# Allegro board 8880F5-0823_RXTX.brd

Outline 581.66 x 429.26 mm; copper layers: TOP, L02_DGND, L03_SIGNAL, L04_DGND, L05_SIGNAL, L06_DGND, L07_SIGNAL, L08_DGND, L09_SIGNAL, L10_DGND, L11_POWER, L12_DGND, L13_POWER, L14_DGND, L15_POWER, L16_DGND, L17_5V, L18_CBIT, L19_DGND, L20_POWER, L21_DGND, L22_POWER, L23_DGND, L24_POWER, L25_DGND, L26_SIGNAL, L27_DGND, L28_SIGNAL, L29_DGND, L30_SIGNAL, L31_DGND, L32_SIGNAL, L33_DGND, BOTTOM. Coordinates in mm from the lower left corner of the outline.

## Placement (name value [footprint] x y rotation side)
BD29  BD120-3A-S8  [FB0805]  129.54 134.62 180 bottom
BD30  BD120-3A-S8  [FB0805]  129.54 146.05 180 bottom
BD31  BD120-3A-S8  [FB0805]  129.54 142.24 0 bottom
BD32  BD120-3A-S8  [FB0805]  513.08 238.76 180 bottom
BD33  BD120-3A-S8  [FB0805]  513.08 242.57 180 bottom
BD34  BD120-3A-S8  [FB0805]  453.64 145.54 0 bottom
BD35  BD120-3A-S8  [FB0805]  453.64 137.92 180 bottom
BD36  BD120-3A-S8  [FB0805]  129.54 138.43 180 bottom
BD37  BD120-3A-S8  [FB0805]  453.64 130.3 180 bottom
BD38  BD120-3A-S8  [FB0805]  513.08 242.57 180 bottom
BD39  BD120-3A-S8  [FB0805]  453.64 141.73 0 bottom
BD40  BD120-3A-S8  [FB0805]  453.64 134.11 180 bottom
BD41  BD120-3A-S8  [FB0805]  513.08 234.95 180 bottom
BD42  BD120-3A-S8  [FB0805]  513.08 231.14 180 bottom
BD43  BD120-3A-S8  [FB0805]  513.08 227.33 180 bottom
BD44  BD120-3A-S8  [FB0805]  129.54 149.86 180 bottom
BR902  330-1-S4  [R0402]  36.83 133.35 270 bottom
C3  0.1U-16-X-S4-MU  [C0402]  184.15 132.33 180 bottom
C4  0.1U-16-X-S4-MU  [C0402]  181.61 132.33 180 bottom
C5  22P-50-N-S4-AVX  [C0402]  221.21 277.48 90 bottom
C6  22P-50-N-S4-AVX  [C0402]  221.21 271.16 270 bottom
C7  0.1U-16-X-S4-MU  [C0402]  110.74 230.12 0 bottom
C8  0.1U-16-X-S4-MU  [C0402]  104.14 215.5 180 bottom
C9  0.1U-16-X-S4-MU  [C0402]  104.24 229.1 180 bottom
CA1  NC/10U-10-X6S-S6-MU  [C0603]  186.05 292.1 0 bottom
CA2  NC/47U-10-X5R-S8-TDK  [C0805]  186.16 294 0 bottom
CA3  NC/10U-10-X6S-S6-MU  [C0603]  174.62 292.1 180 bottom
CA4  NC/47U-10-X5R-S8-TDK  [C0805]  174.52 294 180 bottom
CA5  NC/10U-10-X6S-S6-MU  [C0603]  117.47 290.83 180 bottom
CA6  NC/47U-10-X5R-S8-TDK  [C0805]  117.37 292.74 180 bottom
CA7  NC/10U-10-X6S-S6-MU  [C0603]  169.54 292.1 0 bottom
CA8  NC/47U-10-X5R-S8-TDK  [C0805]  169.65 294 0 bottom
CA9  NC/10U-10-X6S-S6-MU  [C0603]  158.11 292.1 180 bottom
CA10  NC/47U-10-X5R-S8-TDK  [C0805]  158.01 294 180 bottom
CA11  NC/10U-10-X6S-S6-MU  [C0603]  186.05 275.59 0 bottom
CA12  NC/47U-10-X5R-S8-TDK  [C0805]  186.16 277.5 0 bottom
CA13  NC/47U-10-X5R-S8-TDK  [C0805]  202.16 294 0 bottom
CA14  NC/10U-10-X6S-S6-MU  [C0603]  202.06 292.1 0 bottom
CA15  NC/47U-10-X5R-S8-TDK  [C0805]  190.53 294 180 bottom
CA16  NC/10U-10-X6S-S6-MU  [C0603]  190.63 292.1 180 bottom
CA17  NC/47U-10-X5R-S8-TDK  [C0805]  169.65 277.5 0 bottom
CA18  NC/10U-10-X6S-S6-MU  [C0603]  169.54 275.59 0 bottom
CA19  NC/47U-10-X5R-S8-TDK  [C0805]  100.34 249.52 180 bottom
CA20  NC/10U-10-X6S-S6-MU  [C0603]  100.44 247.61 180 bottom
CA21  10U-10-X6S-S6-MU  [C0603]  186.05 289.56 0 bottom
CA22  10U-10-X6S-S6-MU  [C0603]  174.62 289.56 180 bottom
CA23  10U-10-X6S-S6-MU  [C0603]  117.47 288.29 180 bottom
CA24  10U-10-X6S-S6-MU  [C0603]  169.54 289.56 0 bottom
CA25  10U-10-X6S-S6-MU  [C0603]  158.11 289.56 180 bottom
CA26  10U-10-X6S-S6-MU  [C0603]  186.05 273.05 0 bottom
CA27  10U-10-X6S-S6-MU  [C0603]  202.06 289.56 0 bottom
CA28  10U-10-X6S-S6-MU  [C0603]  190.63 289.56 180 bottom
CA29  10U-10-X6S-S6-MU  [C0603]  169.54 273.05 0 bottom
CA30  NC/47U-10-X5R-S8-TDK  [C0805]  95.47 249.57 180 bottom
CA31  10U-10-X6S-S6-MU  [C0603]  95.57 247.66 180 bottom
CA32  NC/10U-10-X6S-S6-MU  [C0603]  202.06 275.59 0 bottom
CA33  NC/47U-10-X5R-S8-TDK  [C0805]  202.16 277.5 0 bottom
CA34  10U-10-X6S-S6-MU  [C0603]  202.06 273.05 0 bottom
CA35  NC/10U-10-X6S-S6-MU  [C0603]  174.62 275.59 180 bottom
CA36  NC/47U-10-X5R-S8-TDK  [C0805]  174.52 277.5 180 bottom
CA37  10U-10-X6S-S6-MU  [C0603]  174.62 273.05 180 bottom
CA38  NC/10U-10-X6S-S6-MU  [C0603]  158.11 275.59 180 bottom
CA39  NC/47U-10-X5R-S8-TDK  [C0805]  158.01 277.5 180 bottom
CA40  10U-10-X6S-S6-MU  [C0603]  158.11 273.05 180 bottom
CB1  0.1U-25-X-S6  [C0603]  116.84 130.81 0 bottom
CB2  10U-16-T-SA  [CODE_A]  116.84 128.27 0 bottom
CB3  0.1U-25-X-S6  [C0603]  472.44 130.81 0 bottom
CB4  10U-16-T-SA  [CODE_A]  472.44 128.27 0 bottom
CB5  0.1U-25-X-S6  [C0603]  556.51 300.99 0 bottom
CB6  10U-16-T-SA  [CODE_A]  556.51 298.45 0 bottom
CB7  0.1U-25-X-S6  [C0603]  223.52 298.45 0 bottom
CB8  10U-16-T-SA  [CODE_A]  223.52 295.91 0 bottom
CB9  0.1U-25-X-S6  [C0603]  23.01 130.71 0 bottom
CB10  10U-25-X7R-SA  [C1206]  22.86 128.27 0 bottom
CB11  0.1U-25-X-S6  [C0603]  484.02 130.71 0 bottom
CB12  10U-25-X7R-SA  [C1206]  483.87 128.27 0 bottom
CB13  0.1U-25-X-S6  [C0603]  547.52 300.89 0 bottom
CB14  10U-25-X7R-SA  [C1206]  547.37 298.45 0 bottom
CB15  0.1U-25-X-S6  [C0603]  12.45 262.13 0 bottom
CB16  10U-25-X7R-SA  [C1206]  12.3 259.69 0 bottom
CB19  0.1U-25-X7R-S4-MU  [C0402]  215.9 17.78 180 bottom
CC1  0.47U-10-X6S-S2-TY  [C0201]  237.98 224.12 90 bottom
CC2  4.7U-10-X6T-S4-MU  [C0402]  236.32 222.4 270 bottom
CC4  0.47U-10-X6S-S2-TY  [C0201]  229.81 247.93 0 bottom
CC6  0.47U-10-X6S-S2-TY  [C0201]  250.17 224.12 90 bottom
CC7  0.47U-10-X6S-S2-TY  [C0201]  229.81 246.66 0 bottom
CC8  0.47U-10-X6S-S2-TY  [C0201]  263.63 224.12 90 bottom
CC9  0.47U-10-X6S-S2-TY  [C0201]  254.61 266.16 270 bottom
CC11  0.47U-10-X6S-S2-TY  [C0201]  251.06 224.12 90 bottom
CC13  0.47U-10-X6S-S2-TY  [C0201]  256.77 224.12 90 bottom
CC15  4.7U-2.5-X6S-S2-MU  [C0201]  259.65 264.95 90 bottom
CC16  NC/4.7U-2.5-X6S-S2-MU  [C0201]  271.64 249.5 0 bottom
CC17  4.7U-2.5-X6S-S2-MU  [C0201]  229.81 253.69 0 bottom
CC19  0.47U-10-X6S-S2-TY  [C0201]  252.83 266.16 270 bottom
CC20  4.7U-10-X6T-S4-MU  [C0402]  254.11 267.66 0 bottom
CC22  0.47U-10-X6S-S2-TY  [C0201]  251.05 266.16 270 bottom
CC23  4.7U-10-X6T-S4-MU  [C0402]  250.34 253.09 270 bottom
CC25  0.47U-10-X6S-S2-TY  [C0201]  272.85 245.18 180 bottom
CC26  0.47U-10-X6S-S2-TY  [C0201]  253.72 266.16 270 bottom
CC27  0.47U-10-X6S-S2-TY  [C0201]  272.85 249.5 180 bottom
CC28  0.47U-10-X6S-S2-TY  [C0201]  259.65 266.16 270 bottom
CC29  0.47U-10-X6S-S2-TY  [C0201]  231.03 253.69 180 bottom
CC30  0.47U-10-X6S-S2-TY  [C0201]  229.81 243.41 0 bottom
CC31  0.47U-10-X6S-S2-TY  [C0201]  249.28 224.12 90 bottom
CC32  0.47U-10-X6S-S2-TY  [C0201]  262.36 224.12 90 bottom
CC33  0.47U-10-X6S-S2-TY  [C0201]  272.85 243.91 180 bottom
CC34  0.47U-10-X6S-S2-TY  [C0201]  251.94 266.16 270 bottom
CC35  0.47U-10-X6S-S2-TY  [C0201]  272.85 241.37 180 bottom
CC36  0.47U-10-X6S-S2-TY  [C0201]  272.85 242.64 180 bottom
CC37  0.47U-10-X6S-S2-TY  [C0201]  247.57 264.95 90 bottom
CC38  NC/4.7U-2.5-X6S-S2-MU  [C0201]  247.57 266.16 270 bottom
CC39  0.47U-10-X6S-S2-TY  [C0201]  231.03 249.2 180 bottom
CC40  4.7U-2.5-X6S-S2-MU  [C0201]  258.5 246.67 180 bottom
CC41  4.7U-2.5-X6S-S2-MU  [C0201]  229.81 249.2 0 bottom
CC42  4.7U-2.5-X6S-S2-MU  [C0201]  251.54 253.03 90 bottom
CD1  0.1U-10-X7R-S2-MU  [C0201]  237.98 225.34 270 top
CD3  0.1U-10-X7R-S2-MU  [C0201]  271.64 241.37 0 top
CD4  0.1U-10-X7R-S2-MU  [C0201]  254.61 264.95 90 top
CD5  0.1U-10-X7R-S2-MU  [C0201]  263.63 225.34 270 top
CD6  0.1U-10-X7R-S2-MU  [C0201]  231.03 246.66 180 top
CD7  0.1U-10-X7R-S2-MU  [C0201]  271.64 242.64 0 top
CD8  0.1U-10-X7R-S2-MU  [C0201]  251.06 225.34 270 top
CD9  0.1U-10-X7R-S2-MU  [C0201]  256.77 225.34 270 top
CD10  0.1U-10-X7R-S2-MU  [C0201]  271.64 249.5 0 top
CD11  0.1U-10-X7R-S2-MU  [C0201]  259.65 264.95 90 top
CD12  0.1U-10-X7R-S2-MU  [C0201]  231.03 253.69 180 top
CD13  0.1U-10-X7R-S2-MU  [C0201]  252.83 264.95 90 top
CD14  0.1U-10-X7R-S2-MU  [C0201]  251.05 264.95 90 top
CD15  0.1U-10-X7R-S2-MU  [C0201]  271.64 245.18 0 top
CD16  0.1U-10-X7R-S2-MU  [C0201]  253.72 264.95 90 top
CD17  0.1U-10-X7R-S2-MU  [C0201]  231.03 247.93 180 top
CD18  0.1U-10-X7R-S2-MU  [C0201]  251.94 264.95 90 top
CD19  0.1U-10-X7R-S2-MU  [C0201]  231.03 243.41 180 top
CD20  0.1U-10-X7R-S2-MU  [C0201]  271.64 243.91 0 top
CD21  0.1U-10-X7R-S2-MU  [C0201]  262.36 225.34 270 top
CD22  0.1U-10-X7R-S2-MU  [C0201]  249.28 225.34 270 top
CD23  0.1U-10-X7R-S2-MU  [C0201]  250.17 225.34 270 top
CD24  0.1U-10-X7R-S2-MU  [C0201]  247.57 264.95 90 top
CD25  0.1U-10-X7R-S2-MU  [C0201]  231.03 249.2 180 top
CSDPS225  V93K_CSDPS_DPS32  [PG_VG93K_PF_DPS32_G8D225]  254 331.47 0 top
CSDPS229  V93K_CSDPS_DPS32  [PG_VG93K_PF_DPS32_G8D229]  180.34 331.47 0 top
CSDPS425  V93K_CSDPS_DPS32  [PG_VG93K_PF_DPS32_G8D425]  254 341.63 0 top
CSDPS429  V93K_CSDPS_DPS32  [PG_VG93K_PF_DPS32_G8D429]  180.34 341.63 0 top
D101/D501  V93K_PS1600 HD  [PG_VG93K_F_HSM_G1D101_501_ND]  327.66 97.79 0 top
D102  V93K_CH  [PG_VG93K_F_G1D102]  327.66 77.47 0 top
D103  V93K_CH  [PG_VG93K_F_G1D103]  327.66 57.15 0 top
D104  V93K_CH  [PG_VG93K_F_G1D104]  327.66 36.83 0 top
D105/D505  V93K_PS1600 HD  [PG_VG93K_F_HSM_G1D105_505_ND]  401.32 97.79 0 top
D106  V93K_CH  [PG_VG93K_F_G1D106]  401.32 77.47 0 top
D107  V93K_CH  [PG_VG93K_F_G1D107]  401.32 57.15 0 top
D108  V93K_CH  [PG_VG93K_F_G1D108]  401.32 36.83 0 top
D109  V93K_CH  [PG_VG93K_F_G2D109]  401.32 331.47 0 top
D110  V93K_CH  [PG_VG93K_F_G2D110]  401.32 351.79 0 top
D111  V93K_CH  [PG_VG93K_F_G2D111]  401.32 372.11 0 top
D112  V93K_CH  [PG_VG93K_F_G2D112]  401.32 392.43 0 top
D113  V93K_CH  [PG_VG93K_F_G2D113]  327.66 331.47 0 top
D114  V93K_CH  [PG_VG93K_F_G2D114]  327.66 351.79 0 top
D115  V93K_CH  [PG_VG93K_F_G2D115]  327.66 372.11 0 top
D116  V93K_CH  [PG_VG93K_F_G2D116]  327.66 392.43 0 top
D117/D517  V93K_PS1600 HD  [PG_VG93K_F_HSM_G3D117_517_ND]  180.34 97.79 0 top
D118  V93K_CH  [PG_VG93K_F_G3D118]  180.34 77.47 0 top
D119  V93K_CH  [PG_VG93K_F_G3D119]  180.34 57.15 0 top
D120  V93K_CH  [PG_VG93K_F_G3D120]  180.34 36.83 0 top
D121/D521  V93K_PS1600 HD  [PG_VG93K_F_HSM_G3D121_521_ND]  254 97.79 0 top
D122  V93K_CH  [PG_VG93K_F_G3D122]  254 77.47 0 top
D123  V93K_CH  [PG_VG93K_F_G3D123]  254 57.15 0 top
D124  V93K_CH  [PG_VG93K_F_G3D124]  254 36.83 0 top
D125  V93K_CH  [PG_VG93K_F_G4D125]  33.02 97.79 0 top
D126  V93K_CH  [PG_VG93K_F_G4D126]  33.02 77.47 0 top
D127  V93K_CH  [PG_VG93K_F_G4D127]  33.02 57.15 0 top
D128  V93K_CH  [PG_VG93K_F_G4D128]  33.02 36.83 0 top
D129  V93K_CH  [PG_VG93K_F_G4D129]  106.68 97.79 0 top
D130  V93K_CH  [PG_VG93K_F_G4D130]  106.68 77.47 0 top
D131  V93K_CH  [PG_VG93K_F_G4D131]  106.68 57.15 0 top
D132  V93K_CH  [PG_VG93K_F_G4D132]  106.68 36.83 0 top
D231  V93K_CH  [PG_VG93K_F_G8D231]  180.34 372.11 0 top
D301  V93K_CH  [PG_VG93K_F_G1D301]  327.66 87.63 0 top
D302  V93K_CH  [PG_VG93K_F_G1D302]  327.66 67.31 0 top
D305  V93K_CH  [PG_VG93K_F_G1D305]  401.32 87.63 0 top
D306  V93K_CH  [PG_VG93K_F_G1D306]  401.32 67.31 0 top
D309  V93K_PSSL  [PG_VG93K_F_PSSL_G2D309_ND]  401.32 341.63 0 top
D313  V93K_PSSL  [PG_VG93K_F_PSSL_G2D313_ND]  327.66 341.63 0 top
D317  V93K_CH  [PG_VG93K_F_G3D317]  180.34 87.63 0 top
D318  V93K_CH  [PG_VG93K_F_G3D318]  180.34 67.31 0 top
D321  V93K_CH  [PG_VG93K_F_G3D321]  254 87.63 0 top
D322  V93K_CH  [PG_VG93K_F_G3D322]  254 67.31 0 top
D431  V93K_CH  [PG_VG93K_F_G8D431]  180.34 382.27 0 top
DPS1  V93K_DPS  [PG_VG93K_F_G1DPS1]  401.32 16.51 0 top
DPS2  V93K_DPS  [PG_VG93K_F_G2DPS2]  327.66 412.75 0 top
DPS3  V93K_DPS  [PG_VG93K_F_G3DPS3]  254 16.51 0 top
DPS8  V93K_DPS  [PG_VG93K_F_G8DPS8]  180.34 412.75 0 top
FD1  -  [FD_040_V2]  159.82 131.98 0 top
FD2  -  [FD_040_V2]  423.24 131.98 0 top
FD3  -  [FD_040_V2]  423.24 297.28 0 top
FD4  -  [FD_040_V2]  156.51 297.46 0 top
FD5  -  [FD_040_V2]  159.82 131.98 180 bottom
FD6  -  [FD_040_V2]  423.24 131.98 180 bottom
FD7  -  [FD_040_V2]  423.24 297.28 180 bottom
FD8  -  [FD_040_V2]  156.51 297.46 180 bottom
FD9  -  [FD_040_V2]  570.23 128.27 180 bottom
FD10  -  [FD_040_V2]  570.23 300.99 0 top
FD11  -  [FD_040_V2]  570.23 300.99 180 bottom
FD12  -  [FD_040_V2]  11.43 300.99 0 top
FD13  -  [FD_040_V2]  11.43 300.99 180 bottom
FD14  -  [FD_040_V2]  11.43 127 0 top
FD15  -  [FD_040_V2]  11.43 127 180 bottom
FD16  -  [FD_040_V2]  570.23 128.27 0 top
GND1  TP01  [TP_040_T]  173.57 294 0 top
GND2  TP01  [TP_040_T]  187.11 294 180 top
GND3  TP01  [TP_040_T]  116.42 292.74 0 top
GND4  TP01  [TP_040_T]  157.06 294 0 top
GND5  TP01  [TP_040_T]  170.6 294 180 top
GND6  TP01  [TP_040_T]  173.57 277.5 0 top
GND7  TP01  [TP_040_T]  203.11 294 180 top
GND8  TP01  [TP_040_T]  189.58 294 0 top
GND9  TP01  [TP_040_T]  170.6 277.5 180 top
GND10  TP01  [TP_040_T]  99.36 249.46 0 top
GND11  TP01  [TP_040_T]  94.49 249.52 0 top
GND12  TP01  [TP_040_T]  203.11 277.5 180 top
GND13  TP01  [TP_040_T]  187.11 277.5 180 top
GND14  TP01  [TP_040_T]  157.06 277.5 0 top
HX8880-F05  REF-CODE-CHIP  [CHIP_CODE]  559.05 279.65 0 top
J1  HDR-2X1-M  [JP_2P_100]  110.24 232.41 270 bottom
J2  HDR-3X1-M  [JP_3P_100]  88.76 205.43 90 bottom
J3  HDR-3X1-M  [JP_3P_100]  88.76 219.15 90 bottom
J4  HDR-2X1-M  [JP_2P_100]  96.27 231.39 90 bottom
J5  HDR-2X1-M  [JP_2P_100]  96.27 243.08 90 bottom
JG_220919AA01  REF-CODE-SOCKET  [SOCKET_CODE]  559.05 284.73 0 top
JG_220919AA02  REF-CODE-SOCKET  [SOCKET_CODE]  559.05 287.27 0 top
K1  G6K-2F-RF-T-5V-SPECIAL  [RL_G6K2FRT_8P_5V_GR]  171.7 219.2 270 bottom
K2  G6K-2F-RF-T-5V-SPECIAL  [RL_G6K2FRT_8P_5V_GR]  205.23 232.92 270 bottom
K3  G6K-2F-RF-T-5V-SPECIAL  [RL_G6K2FRT_8P_5V_GR]  294.39 292.86 0 bottom
K4  G6K-2F-RF-T-5V-SPECIAL  [RL_G6K2FRT_8P_5V_GR]  307.59 292.86 0 bottom
K5  G6K-2F-RF-T-5V-SPECIAL  [RL_G6K2FRT_8P_5V_GR]  347.73 292.86 0 bottom
K6  G6K-2F-RF-T-5V-SPECIAL  [RL_G6K2FRT_8P_5V_GR]  334.26 292.86 0 bottom
K7  G6K-2F-RF-T-5V-SPECIAL  [RL_G6K2FRT_8P_5V_GR]  320.8 292.86 0 bottom
K8  G6K-2F-RF-T-5V-SPECIAL  [RL_G6K2FRT_8P_5V_GR]  267.46 292.86 0 bottom
K9  UA2-5NJ-A-V3  [RL_NECUA2_5V_V3]  219.96 235.46 90 bottom
K10  UA2-5NJ-A-V3  [RL_NECUA2_5V_V3]  111.76 237.24 0 bottom
K11  G6K-2F-RF-T-5V-SPECIAL  [RL_G6K2FRT_8P_5V_GR]  289.56 276.1 180 bottom
K12  UA2-5NJ-A-V3  [RL_NECUA2_5V_V3]  219.96 246.89 90 bottom
K13  UA2-5NJ-A-V3  [RL_NECUA2_5V_V3]  123.7 229.62 180 bottom
K14  UA2-5NJ-A-V3  [RL_NECUA2_5V_V3]  112.01 220.73 180 bottom
K15  UA2-5NJ-A-V3  [RL_NECUA2_5V_V3]  123.99 213.19 180 bottom
K16  G6K-2F-RF-T-5V-SPECIAL  [RL_G6K2FRT_8P_5V_GR]  241.05 292.61 180 bottom
K17  G6K-2F-RF-T-5V-SPECIAL  [RL_G6K2FRT_8P_5V_GR]  254.25 292.86 0 bottom
K18  UB2-5NU-B  [RL_NECUB2_5V]  228.45 274.32 0 bottom
K19  UA2-5NJ-A-V3  [RL_NECUA2_5V_V3]  112.01 213.11 180 bottom
K20  UA2-5NJ-A-V3  [RL_NECUA2_5V_V3]  123.95 220.73 180 bottom
K21  G6K-2F-RF-T-5V-SPECIAL  [RL_G6K2FRT_8P_5V_GR]  280.92 292.86 0 bottom
K22  G6K-2F-RF-T-5V-SPECIAL  [RL_G6K2FRT_8P_5V_GR]  205.23 246.63 270 bottom
K23  G6K-2F-RF-T-5V-SPECIAL  [RL_G6K2FRT_8P_5V_GR]  188.47 232.92 270 bottom
K24  G6K-2F-RF-T-5V-SPECIAL  [RL_G6K2FRT_8P_5V_GR]  171.7 232.92 270 bottom
K25  G6K-2F-RF-T-5V-SPECIAL  [RL_G6K2FRT_8P_5V_GR]  204.98 260.35 270 bottom
K26  G6K-2F-RF-T-5V-SPECIAL  [RL_G6K2FRT_8P_5V_GR]  188.47 246.63 270 bottom
K27  G6K-2F-RF-T-5V-SPECIAL  [RL_G6K2FRT_8P_5V_GR]  171.7 246.63 270 bottom
K28  UA2-5NJ-A-V3  [RL_NECUA2_5V_V3]  100.33 237.24 0 bottom
K29  G6K-2F-RF-T-5V-SPECIAL  [RL_G6K2FRT_8P_5V_GR]  171.7 260.35 270 bottom
K30  G6K-2F-RF-T-5V-SPECIAL  [RL_G6K2FRT_8P_5V_GR]  188.47 260.35 270 bottom
K31  EC2-5NJ-A  [RL_NECEC2_10P_5V]  196.34 276.86 90 bottom
K33  NC/UA2-5NJ-A-V3  [RL_NECUA2_5V_V3]  123.7 237.24 180 bottom
K34  EC2-5NJ-A  [RL_NECEC2_10P_5V]  180.34 293.37 90 bottom
K36  EC2-5NJ-A  [RL_NECEC2_10P_5V]  123.19 292.1 90 bottom
K37  EC2-5NJ-A  [RL_NECEC2_10P_5V]  163.83 293.37 90 bottom
K39  EC2-5NJ-A  [RL_NECEC2_10P_5V]  180.34 276.86 90 bottom
K40  EC2-5NJ-A  [RL_NECEC2_10P_5V]  196.34 293.37 90 bottom
K42  EC2-5NJ-A  [RL_NECEC2_10P_5V]  163.83 276.86 90 bottom
K43  G6K-2F-RF-T-5V-SPECIAL  [RL_G6K2FRT_8P_5V_GR]  269.49 276.1 180 bottom
LD902  LDG-2-S8  [LED_0805]  36.83 130.81 90 top
LOGO1  -  [LOGO_KT_KSMT]  538.48 154.94 0 top
LOGO2  LOGO_HX_Himax  [LOGO_HX_HIMAX]  518.16 138.43 0 top
LQFP176-20X20-P0.4  REF-CODE-CHIP  [CHIP_CODE]  559.05 282.19 0 top
NOREF  -  []  252.51 264.35 90 top
NOREF#2  -  []  309.51 246.66 0 top
NOREF#3  -  []  462.06 293.82 90 top
NOREF#4  -  []  471.21 168.33 0 top
NOREF#5  -  []  399.67 131.89 0 top
NOREF#6  -  []  235.4 289.88 90 top
NOREF#7  -  []  248.33 247.93 0 top
NOREF#8  -  []  331.38 163.52 90 top
NOREF#9  -  []  251.06 225.04 90 top
NOREF#10  -  []  310.41 246.34 90 top
NOREF#11  -  []  175.7 246.08 90 top
NOREF#12  -  []  294.94 296.86 0 top
NOREF#13  -  []  116.27 171.02 0 top
NOREF#14  -  []  167.7 255.15 0 top
NOREF#15  -  []  230.43 243.09 0 top
NOREF#16  -  []  475.04 195.66 0 top
NOREF#17  -  []  254.29 205.56 90 top
NOREF#18  -  []  172.08 289.11 90 top
NOREF#19  -  []  328.42 129.74 90 top
NOREF#20  -  []  366.88 222.7 0 top
NOREF#21  -  []  118.45 239.39 0 top
NOREF#22  -  []  175.7 209.49 90 top
NOREF#23  -  []  310.41 183.09 90 top
NOREF#24  -  []  331.94 264.65 90 top
NOREF#25  -  []  103.93 235.64 90 top
NOREF#26  -  []  220.36 237.06 0 top
NOREF#27  -  []  465.31 230.2 0 top
NOREF#28  -  []  419.4 171.64 0 top
NOREF#29  -  []  330.49 223.52 90 top
NOREF#30  -  []  184.47 178.86 90 top
NOREF#31  -  []  383.07 180.2 90 top
NOREF#32  -  []  481.96 276.41 90 top
NOREF#33  -  []  167.7 187.92 90 top
NOREF#34  -  []  393.31 131.89 90 top
NOREF#35  -  []  383.09 257.11 0 top
NOREF#36  -  []  185.2 292.55 90 top
NOREF#37  -  []  167.7 147.28 90 top
NOREF#38  -  []  317.83 197.63 0 top
NOREF#39  -  []  201.23 206.29 90 top
NOREF#40  -  []  258.61 131.69 90 top
NOREF#41  -  []  262.04 164.74 0 top
NOREF#42  -  []  342.68 224.74 90 top
NOREF#43  -  []  385.19 273.11 0 top
NOREF#44  -  []  314.71 129.74 90 top
NOREF#45  -  []  259.33 264.35 90 top
NOREF#46  -  []  306.27 216.63 90 top
NOREF#47  -  []  300.36 237.06 0 top
NOREF#48  -  []  310.43 186.34 0 top
NOREF#49  -  []  223.15 271.32 90 top
NOREF#50  -  []  284.36 280.1 0 top
NOREF#51  -  []  310.43 249.52 0 top
NOREF#52  -  []  166.06 175.58 90 top
NOREF#53  -  []  329.85 164.74 0 top
NOREF#54  -  []  396.55 289.12 0 top
NOREF#55  -  []  477.24 239.09 0 top
NOREF#56  -  []  329.28 223.82 90 top
NOREF#57  -  []  209.23 222.95 90 top
NOREF#58  -  []  222.11 180.71 0 top
NOREF#59  -  []  423.45 146.93 90 top
NOREF#60  -  []  354.08 286.96 90 top
NOREF#61  -  []  118.7 217.73 90 top
NOREF#62  -  []  106.76 215.26 0 top
NOREF#63  -  []  352.25 241.05 90 top
NOREF#64  -  []  127.95 195.15 0 top
NOREF#65  -  []  368.28 297.12 0 top
NOREF#66  -  []  248.96 164.72 0 top
NOREF#67  -  []  376.98 257.11 0 top
NOREF#68  -  []  100.98 195.15 0 top
NOREF#69  -  []  304.61 144.34 0 top
NOREF#70  -  []  453.88 186.77 0 top
NOREF#71  -  []  209.23 246.08 90 top
NOREF#72  -  []  259.33 265.56 90 top
NOREF#73  -  []  167.7 214 90 top
NOREF#74  -  []  253.72 204.65 90 top
NOREF#75  -  []  234.33 228.13 90 top
NOREF#76  -  []  219.76 297.18 0 top
NOREF#77  -  []  283.21 282 0 top
NOREF#78  -  []  327.7 131.19 90 top
NOREF#79  -  []  388.43 180.15 0 top
NOREF#80  -  []  403.99 188.15 0 top
NOREF#81  -  []  400.85 233.11 0 top
NOREF#82  -  []  456.04 179.06 0 top
NOREF#83  -  []  327.57 264.65 90 top
NOREF#84  -  []  248.21 132.69 90 top
NOREF#85  -  []  238.3 164.74 90 top
NOREF#86  -  []  118.96 179.19 0 top
NOREF#87  -  []  337.09 164.74 90 top
NOREF#88  -  []  410.52 241.11 0 top
NOREF#89  -  []  250.17 223.82 90 top
NOREF#90  -  []  352.25 181.69 0 top
NOREF#91  -  []  272.25 249.82 0 top
NOREF#92  -  []  338.36 288.91 90 top
NOREF#93  -  []  175.7 137.37 90 top
NOREF#94  -  []  319.33 243.63 90 top
NOREF#95  -  []  211.11 160.4 90 top
NOREF#96  -  []  262.36 163.82 90 top
NOREF#97  -  []  309.21 193.37 0 top
NOREF#98  -  []  306.85 211.67 0 top
NOREF#99  -  []  210.86 214.75 90 top
NOREF#100  -  []  419.9 272.82 90 top
NOREF#101  -  []  311.15 219.63 90 top
NOREF#102  -  []  261.63 233.83 90 top
NOREF#103  -  []  272.25 243.59 90 top
NOREF#104  -  []  354.37 130.67 90 top
NOREF#105  -  []  351.34 189.5 0 top
NOREF#106  -  []  237.83 197.63 0 top
NOREF#107  -  []  256.45 164.72 0 top
NOREF#108  -  []  266.74 143.19 0 top
NOREF#109  -  []  451.68 239.34 0 top
NOREF#110  -  []  273.09 288.31 90 top
NOREF#111  -  []  251.62 264.35 90 top
NOREF#112  -  []  328.96 164.72 0 top
NOREF#113  -  []  253.4 265.56 0 top
NOREF#114  -  []  270.29 135.24 90 top
NOREF#115  -  []  310.43 254.01 0 top
NOREF#116  -  []  127.55 191.95 90 top
NOREF#117  -  []  318.3 164.74 90 top
NOREF#118  -  []  106.11 234.24 0 top
NOREF#119  -  []  201.23 186.57 0 top
NOREF#120  -  []  110.21 214.71 0 top
NOREF#121  -  []  404.4 289.17 90 top
NOREF#122  -  []  248.96 224.74 0 top
NOREF#123  -  []  105.83 190.55 90 top
NOREF#124  -  []  376.98 241.11 0 top
NOREF#125  -  []  247.57 204.65 90 top
NOREF#126  -  []  419.22 257.37 90 top
NOREF#127  -  []  272.25 183.59 90 top
NOREF#128  -  []  119.99 214.79 0 top
NOREF#129  -  []  247.25 265.55 0 top
NOREF#130  -  []  380.59 271.21 0 top
NOREF#131  -  []  229.21 247.61 0 top
NOREF#132  -  []  211.11 173.86 90 top
NOREF#133  -  []  230.43 248.88 0 top
NOREF#134  -  []  257.9 186.99 0 top
NOREF#135  -  []  253.4 264.35 90 top
NOREF#136  -  []  184.47 229.07 90 top
NOREF#137  -  []  115.36 235.64 0 top
NOREF#138  -  []  185.2 276.04 90 top
NOREF#139  -  []  230.43 249.52 0 top
NOREF#140  -  []  165.8 158.5 0 top
NOREF#141  -  []  201.49 165.4 90 top
NOREF#142  -  []  251.22 253.63 0 top
NOREF#143  -  []  377.23 257.16 90 top
NOREF#144  -  []  336.77 163.82 90 top
NOREF#145  -  []  119.95 222.33 0 top
NOREF#146  -  []  192.47 195.52 90 top
NOREF#147  -  []  230.43 189.52 0 top
NOREF#148  -  []  251.22 193.63 0 top
NOREF#149  -  []  184.47 231.27 90 top
NOREF#150  -  []  339.33 265.55 0 top
NOREF#151  -  []  302.11 252.14 0 top
NOREF#152  -  []  257.9 246.99 0 top
NOREF#153  -  []  175.7 205.19 90 top
NOREF#154  -  []  167.7 159.65 0 top
NOREF#155  -  []  182.57 185.42 90 top
NOREF#156  -  []  328.96 224.72 0 top
NOREF#157  -  []  175.8 187.82 90 top
NOREF#158  -  []  209.23 205.19 90 top
NOREF#159  -  []  331.62 204.35 90 top
NOREF#160  -  []  258.2 246.67 0 top
NOREF#161  -  []  460.93 166.93 90 top
NOREF#162  -  []  209.49 155.13 90 top
NOREF#163  -  []  471.21 175.95 90 top
NOREF#164  -  []  201.23 219.75 90 top
NOREF#165  -  []  230.43 183.09 90 top
NOREF#166  -  []  259.33 265.56 0 top
NOREF#167  -  []  334.29 204.35 90 top
NOREF#168  -  []  418.63 131.94 90 top
NOREF#169  -  []  310.43 247.61 0 top
NOREF#170  -  []  309.51 186.66 0 top
NOREF#171  -  []  470.71 227 90 top
NOREF#172  -  []  368.03 249.11 0 top
NOREF#173  -  []  122.19 214.79 0 top
NOREF#174  -  []  167.7 178.86 90 top
NOREF#175  -  []  419.47 289.12 90 top
NOREF#176  -  []  310.43 186.34 90 top
NOREF#177  -  []  297.71 276.09 0 top
NOREF#178  -  []  251.38 224.74 90 top
NOREF#179  -  []  271.34 249.5 0 top
NOREF#180  -  []  201.21 273.5 90 top
NOREF#181  -  []  251.86 252.43 90 top
NOREF#182  -  []  272.25 189.18 90 top
NOREF#183  -  []  108.27 178.64 0 top
NOREF#184  -  []  317.98 223.82 90 top
NOREF#185  -  []  75.98 271.33 90 top
NOREF#186  -  []  351.04 189.18 0 top
NOREF#187  -  []  465.81 179.15 0 top
NOREF#188  -  []  460.89 174.46 90 top
NOREF#189  -  []  468.01 222.58 0 top
NOREF#190  -  []  201.91 159.1 90 top
NOREF#191  -  []  377.48 289.17 90 top
NOREF#192  -  []  209.59 160.9 90 top
NOREF#193  -  []  182.57 171.96 90 top
NOREF#194  -  []  410.84 163.64 90 top
NOREF#195  -  []  302.11 180.71 0 top
NOREF#196  -  []  300.36 177.06 0 top
NOREF#197  -  []  230.43 243.09 90 top
NOREF#198  -  []  230.43 246.34 0 top
NOREF#199  -  []  106.76 222.88 0 top
NOREF#200  -  []  351.58 288.86 0 top
NOREF#201  -  []  182.57 240.28 0 top
NOREF#202  -  []  167.7 215.35 90 top
NOREF#203  -  []  165.8 212.85 0 top
NOREF#204  -  []  192.57 187.82 90 top
NOREF#205  -  []  201.23 241.43 90 top
NOREF#206  -  []  331.62 265.56 90 top
NOREF#207  -  []  272.55 242.64 0 top
NOREF#208  -  []  250.74 164.74 0 top
NOREF#209  -  []  390.53 180.15 0 top
NOREF#210  -  []  419.73 131.89 90 top
NOREF#211  -  []  271.34 185.18 0 top
NOREF#212  -  []  351.04 249.82 0 top
NOREF#213  -  []  167.7 227.72 0 top
NOREF#214  -  []  552.76 299.72 0 top
NOREF#215  -  []  247.78 132.14 90 top
NOREF#216  -  []  386.53 148.15 90 top
NOREF#217  -  []  405.93 224.56 90 top
NOREF#218  -  []  408.02 271.47 0 top
NOREF#219  -  []  400.24 195.88 90 top
NOREF#220  -  []  121.9 231.22 0 top
NOREF#221  -  []  404.15 257.37 0 top
NOREF#222  -  []  303.26 152.34 0 top
NOREF#223  -  []  266.74 272.1 0 top
NOREF#224  -  []  400.85 297.12 0 top
NOREF#225  -  []  259.84 133.29 90 top
NOREF#226  -  []  410.52 289.12 0 top
NOREF#227  -  []  339.33 265.55 0 top
NOREF#228  -  []  175.7 177.76 90 top
NOREF#229  -  []  247.25 264.35 90 top
NOREF#230  -  []  377.23 241.16 90 top
NOREF#231  -  []  380.59 239.21 0 top
NOREF#232  -  []  456.08 214.96 0 top
NOREF#233  -  []  397.8 179.6 90 top
NOREF#234  -  []  167.7 138.47 90 top
NOREF#235  -  []  184.47 161 90 top
NOREF#236  -  []  290.64 288.86 0 top
NOREF#237  -  []  478.57 277.31 90 top
NOREF#238  -  []  383.09 257.11 0 top
NOREF#239  -  []  351.04 181.69 0 top
NOREF#240  -  []  75.98 273.87 90 top
NOREF#241  -  []  342.36 225.04 90 top
NOREF#242  -  []  182.57 254 90 top
NOREF#243  -  []  226.27 156.63 90 top
NOREF#244  -  []  321.35 296.86 0 top
NOREF#245  -  []  331.06 163.82 90 top
NOREF#246  -  []  290.11 280.1 0 top
NOREF#247  -  []  369.38 241.11 0 top
NOREF#248  -  []  336.45 224.72 0 top
NOREF#249  -  []  342.68 223.52 90 top
NOREF#250  -  []  262.68 163.52 90 top
NOREF#251  -  []  409.43 139.89 0 top
NOREF#252  -  []  407.71 217.61 0 top
NOREF#253  -  []  201.49 151.93 90 top
NOREF#254  -  []  271.04 184.23 0 top
NOREF#255  -  []  215.96 177.06 0 top
NOREF#256  -  []  336.77 225.04 90 top
NOREF#257  -  []  182.82 148.4 90 top
NOREF#258  -  []  322.23 233.13 0 top
NOREF#259  -  []  167.7 159.65 90 top
NOREF#260  -  []  168.69 276.04 90 top
NOREF#261  -  []  392.04 289.12 90 top
NOREF#262  -  []  194.09 214.75 90 top
NOREF#263  -  []  201.23 227.72 90 top
NOREF#264  -  []  310.41 243.09 90 top
NOREF#265  -  []  330.51 288.86 0 top
NOREF#266  -  []  394.05 287.22 0 top
NOREF#267  -  []  240.83 194.63 0 top
NOREF#268  -  []  302.11 240.71 0 top
NOREF#269  -  []  272.25 241.05 90 top
NOREF#270  -  []  403.41 209.61 0 top
NOREF#271  -  []  200.98 260.9 90 top
NOREF#272  -  []  392.47 256.66 90 top
NOREF#273  -  []  351.34 183.91 0 top
NOREF#274  -  []  410.78 131.89 0 top
NOREF#275  -  []  259.33 205.56 90 top
NOREF#276  -  []  93.76 290.38 90 top
NOREF#277  -  []  221.56 231.46 0 top
NOREF#278  -  []  329.6 163.52 90 top
NOREF#279  -  []  199.59 158.5 90 top
NOREF#280  -  []  330.18 242.88 0 top
NOREF#281  -  []  248.96 224.72 0 top
NOREF#282  -  []  215.96 177.06 0 top
NOREF#283  -  []  396.55 225.11 0 top
NOREF#284  -  []  406.52 131.89 90 top
NOREF#285  -  []  306.71 131.64 0 top
NOREF#286  -  []  309.21 248.88 0 top
NOREF#287  -  []  311.15 159.63 90 top
NOREF#288  -  []  311.44 288.86 0 top
NOREF#289  -  []  192.47 257.6 90 top
NOREF#290  -  []  201.49 176.66 90 top
NOREF#291  -  []  120.24 171.1 0 top
NOREF#292  -  []  272.55 182.64 0 top
NOREF#293  -  []  451.64 179.06 0 top
NOREF#294  -  []  229.51 243.41 0 top
NOREF#295  -  []  209.59 147.43 90 top
NOREF#296  -  []  404.15 225.11 0 top
NOREF#297  -  []  265.64 280.1 0 top
NOREF#298  -  []  167.7 192.32 90 top
NOREF#299  -  []  251.54 252.73 90 top
NOREF#300  -  []  405.5 225.11 90 top
NOREF#301  -  []  209.49 177.76 90 top
NOREF#302  -  []  332.83 264.65 90 top
NOREF#303  -  []  254.29 265.55 0 top
NOREF#304  -  []  419.65 256.92 90 top
NOREF#305  -  []  230.43 253.37 90 top
NOREF#306  -  []  418.12 289.12 0 top
NOREF#307  -  []  122.15 222.33 0 top
NOREF#308  -  []  209.23 250.38 90 top
NOREF#309  -  []  263.31 164.72 0 top
NOREF#310  -  []  453.88 195.91 0 top
NOREF#311  -  []  168.13 213.45 90 top
NOREF#312  -  []  450.03 166.93 0 top
NOREF#313  -  []  175.7 264.1 90 top
NOREF#314  -  []  473.79 239.64 0 top
NOREF#315  -  []  306.83 209.63 90 top
NOREF#316  -  []  246.23 173.13 0 top
NOREF#317  -  []  382.82 163.39 0 top
NOREF#318  -  []  459.28 236.14 0 top
NOREF#319  -  []  251.38 163.52 90 top
NOREF#320  -  []  330.18 182.88 0 top
NOREF#321  -  []  331.22 253.63 0 top
NOREF#322  -  []  192.57 160.9 90 top
NOREF#323  -  []  308.14 296.86 0 top
NOREF#324  -  []  122.15 187.53 0 top
NOREF#325  -  []  263.63 163.82 90 top
NOREF#326  -  []  209.49 150.83 90 top
NOREF#327  -  []  405.93 288.67 90 top
NOREF#328  -  []  351.34 249.5 0 top
NOREF#329  -  []  271.82 134.74 90 top
NOREF#330  -  []  301.56 190.49 0 top
NOREF#331  -  []  343.95 163.52 90 top
NOREF#332  -  []  184.47 233.47 90 top
NOREF#333  -  []  371.73 297.12 0 top
NOREF#334  -  []  352.55 243.91 0 top
NOREF#335  -  []  254.29 205.56 0 top
NOREF#336  -  []  209.23 191.22 90 top
NOREF#337  -  []  352.55 183.91 0 top
NOREF#338  -  []  403.99 180.15 0 top
NOREF#339  -  []  303.84 288.86 0 top
NOREF#340  -  []  270.04 280.1 0 top
NOREF#341  -  []  327.25 205.56 90 top
NOREF#342  -  []  286.55 288.41 90 top
NOREF#343  -  []  405.93 240.66 90 top
NOREF#344  -  []  167.7 151.68 90 top
NOREF#345  -  []  106.29 174.19 90 top
NOREF#346  -  []  371.48 241.11 0 top
NOREF#347  -  []  217.83 234.63 90 top
NOREF#348  -  []  106.03 217.88 90 top
NOREF#349  -  []  184.47 192.32 90 top
NOREF#350  -  []  184.47 215.35 90 top
NOREF#351  -  []  118.33 273.87 90 top
NOREF#352  -  []  379.01 272.66 90 top
NOREF#353  -  []  423.61 184.62 90 top
NOREF#354  -  []  201.23 187.92 90 top
NOREF#355  -  []  390.94 241.16 90 top
NOREF#356  -  []  518.38 257.36 90 top
NOREF#357  -  []  259.33 205.56 0 top
NOREF#358  -  []  313.22 288.31 90 top
NOREF#359  -  []  378.75 224.15 90 top
NOREF#360  -  []  352.25 181.05 90 top
NOREF#361  -  []  184.47 178.86 90 top
NOREF#362  -  []  124.64 171.1 0 top
NOREF#363  -  []  310.43 243.09 0 top
NOREF#364  -  []  222.67 298 90 top
NOREF#365  -  []  383.07 163.44 90 top
NOREF#366  -  []  419.64 256.82 90 top
NOREF#367  -  []  392.47 288.67 90 top
NOREF#368  -  []  398.65 233.11 0 top
NOREF#369  -  []  112.67 178.64 0 top
NOREF#370  -  []  184.47 147.28 90 top
NOREF#371  -  []  302.11 192.14 0 top
NOREF#372  -  []  209.33 215.25 90 top
NOREF#373  -  []  256.45 224.72 0 top
NOREF#374  -  []  327.25 205.56 0 top
NOREF#375  -  []  310.73 243.41 0 top
NOREF#376  -  []  155.57 275.14 90 top
NOREF#377  -  []  343.83 231.63 90 top
NOREF#378  -  []  184.47 190.12 90 top
NOREF#379  -  []  201.23 192.32 90 top
NOREF#380  -  []  201.23 214 0 top
NOREF#381  -  []  166.06 216.47 90 top
NOREF#382  -  []  409.17 281.37 0 top
NOREF#383  -  []  369.38 257.11 0 top
NOREF#384  -  []  339.33 205.55 0 top
NOREF#385  -  []  471.59 130.36 90 top
NOREF#386  -  []  373.68 249.11 0 top
NOREF#387  -  []  209.23 236.67 90 top
NOREF#388  -  []  230.73 253.69 0 top
NOREF#389  -  []  336.45 164.74 0 top
NOREF#390  -  []  175.8 242.68 90 top
NOREF#391  -  []  310.43 253.37 0 top
NOREF#392  -  []  414.82 249.11 0 top
NOREF#393  -  []  352.55 242.64 0 top
NOREF#394  -  []  249.6 163.52 90 top
NOREF#395  -  []  257.09 223.52 90 top
NOREF#396  -  []  221.56 182.89 0 top
NOREF#397  -  []  310.43 246.34 0 top
NOREF#398  -  []  167.7 178.86 90 top
NOREF#399  -  []  199.59 171.96 90 top
NOREF#400  -  []  167.7 145.93 0 top
NOREF#401  -  []  333.4 265.55 0 top
NOREF#402  -  []  292.74 296.86 0 top
NOREF#403  -  []  209.23 243.88 90 top
NOREF#404  -  []  108.01 214.71 0 top
NOREF#405  -  []  241.82 167.13 90 top
NOREF#406  -  []  396.55 225.11 0 top
NOREF#407  -  []  411.26 163.19 90 top
NOREF#408  -  []  192.47 236.67 90 top
NOREF#409  -  []  310.43 253.37 90 top
NOREF#410  -  []  249.6 223.52 90 top
NOREF#411  -  []  310.43 183.09 0 top
NOREF#412  -  []  177.33 228.47 90 top
NOREF#413  -  []  119.7 238.84 0 top
NOREF#414  -  []  199.33 212.85 90 top
NOREF#415  -  []  337.9 186.35 90 top
NOREF#416  -  []  272.24 189.18 90 top
NOREF#417  -  []  377.23 273.11 0 top
NOREF#418  -  []  217.83 174.63 90 top
NOREF#419  -  []  175.7 150.58 90 top
NOREF#420  -  []  387.08 171.64 0 top
NOREF#421  -  []  262.04 164.72 0 top
NOREF#422  -  []  330.73 205.56 90 top
NOREF#423  -  []  217.41 213.24 0 top
NOREF#424  -  []  375.73 199.18 90 top
NOREF#425  -  []  369.63 273.11 0 top
NOREF#426  -  []  300.74 286.96 90 top
NOREF#427  -  []  259.65 205.86 90 top
NOREF#428  -  []  301.56 179.06 0 top
NOREF#429  -  []  237.2 296.61 0 top
NOREF#430  -  []  471.21 211.76 90 top
NOREF#431  -  []  124.35 222.33 0 top
NOREF#432  -  []  250.49 163.52 90 top
NOREF#433  -  []  229.51 187.93 0 top
NOREF#434  -  []  375.22 163.39 0 top
NOREF#435  -  []  384.36 131.89 0 top
NOREF#436  -  []  192.47 202.99 90 top
NOREF#437  -  []  259.33 265.55 0 top
NOREF#438  -  []  398.65 257.37 0 top
NOREF#439  -  []  96.58 195.15 0 top
NOREF#440  -  []  409.49 180.15 0 top
NOREF#441  -  []  118.33 289.48 90 top
NOREF#442  -  []  295.96 237.06 0 top
NOREF#443  -  []  373.68 265.11 0 top
NOREF#444  -  []  415.08 139.89 0 top
NOREF#445  -  []  175.7 259.8 90 top
NOREF#446  -  []  127.3 228.02 90 top
NOREF#447  -  []  118.7 188.08 0 top
NOREF#448  -  []  468.68 129.54 0 top
NOREF#449  -  []  353.35 288.41 90 top
NOREF#450  -  []  386.46 131.89 0 top
NOREF#451  -  []  184.47 233.47 90 top
NOREF#452  -  []  301.56 231.46 0 top
NOREF#453  -  []  273.09 288.41 90 top
NOREF#454  -  []  339.97 204.35 90 top
NOREF#455  -  []  175.8 174.36 90 top
NOREF#456  -  []  263.95 223.52 90 top
NOREF#457  -  []  112.16 238.84 0 top
NOREF#458  -  []  317.66 224.72 0 top
NOREF#459  -  []  320.94 211.63 90 top
NOREF#460  -  []  320.94 151.63 90 top
NOREF#461  -  []  331.38 164.74 90 top
NOREF#462  -  []  346.27 129.42 0 top
NOREF#463  -  []  393.74 131.44 90 top
NOREF#464  -  []  467.51 230.2 0 top
NOREF#465  -  []  333.72 265.86 90 top
NOREF#466  -  []  399.39 161.74 0 top
NOREF#467  -  []  338.2 186.67 0 top
NOREF#468  -  []  461.96 174.55 0 top
NOREF#469  -  []  419.9 272.92 90 top
NOREF#470  -  []  383.73 198.08 90 top
NOREF#471  -  []  352.55 181.37 0 top
NOREF#472  -  []  459.28 192.71 90 top
NOREF#473  -  []  378.75 224.05 90 top
NOREF#474  -  []  406.65 223.21 90 top
NOREF#475  -  []  266.74 143.19 0 top
NOREF#476  -  []  450.03 225.6 0 top
NOREF#477  -  []  470.71 183.57 90 top
NOREF#478  -  []  260.83 174.63 90 top
NOREF#479  -  []  122.19 247.3 90 top
NOREF#480  -  []  390.94 273.16 90 top
NOREF#481  -  []  396.55 273.11 0 top
NOREF#482  -  []  378.75 256.66 90 top
NOREF#483  -  []  275.12 271.65 90 top
NOREF#484  -  []  118.45 239.39 0 top
NOREF#485  -  []  412.62 249.11 0 top
NOREF#486  -  []  388.43 146.88 0 top
NOREF#487  -  []  284.79 272.65 90 top
NOREF#488  -  []  210.86 201.29 90 top
NOREF#489  -  []  201.66 213.45 90 top
NOREF#490  -  []  247.25 265.55 0 top
NOREF#491  -  []  124.35 187.53 0 top
NOREF#492  -  []  201.23 200.54 90 top
NOREF#493  -  []  392.24 199.18 90 top
NOREF#494  -  []  101.29 247.16 90 top
NOREF#495  -  []  405.5 289.12 90 top
NOREF#496  -  []  184.47 200.54 0 top
NOREF#497  -  []  352.55 249.5 0 top
NOREF#498  -  []  420.62 287.22 90 top
NOREF#499  -  []  405.93 224.66 90 top
NOREF#500  -  []  250.73 265.56 0 top
NOREF#501  -  []  230.43 188.88 90 top
NOREF#502  -  []  220.36 177.06 0 top
NOREF#503  -  []  320.83 194.63 0 top
NOREF#504  -  []  230.73 249.2 0 top
NOREF#505  -  []  390.69 273.11 0 top
NOREF#506  -  []  253.4 265.56 90 top
NOREF#507  -  []  230.43 187.61 0 top
NOREF#508  -  []  461.96 166.93 0 top
NOREF#509  -  []  425.23 180.72 90 top
NOREF#510  -  []  422.95 163.69 90 top
NOREF#511  -  []  237.66 224.72 0 top
NOREF#512  -  []  367.73 274.38 90 top
NOREF#513  -  []  250.73 265.55 0 top
NOREF#514  -  []  390.53 188.15 0 top
NOREF#515  -  []  387.8 210.63 90 top
NOREF#516  -  []  128.24 171.1 0 top
NOREF#517  -  []  230.41 246.34 90 top
NOREF#518  -  []  419.47 241.11 90 top
NOREF#519  -  []  339.33 265.56 0 top
NOREF#520  -  []  167.7 173.11 0 top
NOREF#521  -  []  263.71 288.86 0 top
NOREF#522  -  []  247.78 140.14 0 top
NOREF#523  -  []  414.82 297.12 0 top
NOREF#524  -  []  247.57 205.86 90 top
NOREF#525  -  []  420.88 129.99 90 top
NOREF#526  -  []  115.61 191.95 0 top
NOREF#527  -  []  478.57 259.9 90 top
NOREF#528  -  []  264.72 272.65 90 top
NOREF#529  -  []  313.56 131.64 90 top
NOREF#530  -  []  330.49 164.74 90 top
NOREF#531  -  []  331.54 192.73 90 top
NOREF#532  -  []  230.43 187.61 90 top
NOREF#533  -  []  412.62 241.11 0 top
NOREF#534  -  []  281.47 296.86 0 top
NOREF#535  -  []  342.63 296.86 0 top
NOREF#536  -  []  332.51 205.55 0 top
NOREF#537  -  []  322.23 173.13 0 top
NOREF#538  -  []  293.66 272.15 90 top
NOREF#539  -  []  465.45 290.38 90 top
NOREF#540  -  []  175.8 147.18 90 top
NOREF#541  -  []  343.98 288.86 0 top
NOREF#542  -  []  423.2 146.88 0 top
NOREF#543  -  []  310.73 189.2 0 top
NOREF#544  -  []  229.05 271.67 0 top
NOREF#545  -  []  401.89 180.15 0 top
NOREF#546  -  []  259.65 264.65 90 top
NOREF#547  -  []  383.09 273.11 0 top
NOREF#548  -  []  456.08 239.34 0 top
NOREF#549  -  []  230.73 247.93 0 top
NOREF#550  -  []  272.24 249.18 90 top
NOREF#551  -  []  277.17 288.86 0 top
NOREF#552  -  []  263.14 282 0 top
NOREF#553  -  []  450.03 191.31 0 top
NOREF#554  -  []  317.98 163.82 90 top
NOREF#555  -  []  472.86 217.98 90 top
NOREF#556  -  []  175.8 256.4 90 top
NOREF#557  -  []  334.29 265.55 0 top
NOREF#558  -  []  465.81 214.96 0 top
NOREF#559  -  []  332.61 296.86 0 top
NOREF#560  -  []  230.83 164.63 0 top
NOREF#561  -  []  332.51 265.55 0 top
NOREF#562  -  []  395.2 233.11 0 top
NOREF#563  -  []  272.55 181.37 0 top
NOREF#564  -  []  392.21 131.94 90 top
NOREF#565  -  []  272.24 243.59 90 top
NOREF#566  -  []  411.52 146.43 90 top
NOREF#567  -  []  229.51 247.93 0 top
NOREF#568  -  []  343.31 224.74 0 top
NOREF#569  -  []  396.55 289.12 0 top
NOREF#570  -  []  199.08 254 90 top
NOREF#571  -  []  378.58 289.12 90 top
NOREF#572  -  []  168.13 199.99 90 top
NOREF#573  -  []  201.66 227.17 90 top
NOREF#574  -  []  184.47 145.93 90 top
NOREF#575  -  []  330.73 265.56 90 top
NOREF#576  -  []  167.7 200.54 0 top
NOREF#577  -  []  96.58 195.15 0 top
NOREF#578  -  []  327.25 265.56 0 top
NOREF#579  -  []  250.73 204.35 90 top
NOREF#580  -  []  184.47 241.43 0 top
NOREF#581  -  []  167.7 151.68 90 top
NOREF#582  -  []  184.47 260.9 90 top
NOREF#583  -  []  271.34 183.91 0 top
NOREF#584  -  []  417.2 163.64 0 top
NOREF#585  -  []  400.79 154.88 0 top
NOREF#586  -  []  405.5 273.11 90 top
NOREF#587  -  []  112.41 222.33 0 top
NOREF#588  -  []  387.08 188.15 0 top
NOREF#589  -  []  388.35 217.36 0 top
NOREF#590  -  []  310.43 193.37 90 top
NOREF#591  -  []  272.24 249.18 90 top
NOREF#592  -  []  351.04 242.96 0 top
NOREF#593  -  []  317.57 269.63 90 top
NOREF#594  -  []  463.11 230.2 0 top
NOREF#595  -  []  386.53 164.91 90 top
NOREF#596  -  []  461.86 230.75 0 top
NOREF#597  -  []  265.64 135.19 0 top
NOREF#598  -  []  251.06 223.82 90 top
NOREF#599  -  []  405.93 256.82 90 top
NOREF#600  -  []  251.94 265.86 90 top
NOREF#601  -  []  314.33 168.13 90 top
NOREF#602  -  []  403.99 163.64 0 top
NOREF#603  -  []  351.83 288.91 90 top
NOREF#604  -  []  371.73 289.12 0 top
NOREF#605  -  []  373.83 192.28 0 top
NOREF#606  -  []  310.43 188.88 0 top
NOREF#607  -  []  328.33 187.93 0 top
NOREF#608  -  []  192.57 201.79 90 top
NOREF#609  -  []  301.56 250.49 0 top
NOREF#610  -  []  101.82 287.84 90 top
NOREF#611  -  []  409.99 146.93 90 top
NOREF#612  -  []  184.47 247.18 90 top
NOREF#613  -  []  352.24 241.05 90 top
NOREF#614  -  []  263.95 164.74 90 top
NOREF#615  -  []  295.96 188.49 0 top
NOREF#616  -  []  167.7 242.78 90 top
NOREF#617  -  []  230.43 186.34 0 top
NOREF#618  -  []  405.5 241.11 90 top
NOREF#619  -  []  298.49 288.91 90 top
NOREF#620  -  []  279.7 155.38 0 top
NOREF#621  -  []  201.66 240.88 90 top
NOREF#622  -  []  352.24 189.18 90 top
NOREF#623  -  []  168.69 292.55 90 top
NOREF#624  -  []  451.68 186.77 0 top
NOREF#625  -  []  369.63 273.11 0 top
NOREF#626  -  []  285.02 288.91 90 top
NOREF#627  -  []  398.65 265.37 0 top
NOREF#628  -  []  331.86 192.43 90 top
NOREF#629  -  []  259.65 264.65 90 top
NOREF#630  -  []  390.94 289.17 90 top
NOREF#631  -  []  250.49 223.52 90 top
NOREF#632  -  []  182.82 257.62 90 top
NOREF#633  -  []  390.34 192.28 90 top
NOREF#634  -  []  272.8 145.48 90 top
NOREF#635  -  []  167.7 161 90 top
NOREF#636  -  []  381.2 226.12 90 top
NOREF#637  -  []  265.81 296.86 0 top
NOREF#638  -  []  398.53 144.98 90 top
NOREF#639  -  []  208.98 264.1 90 top
NOREF#640  -  []  167.7 132.72 0 top
NOREF#641  -  []  330.49 163.52 90 top
NOREF#642  -  []  302.11 142.44 0 top
NOREF#643  -  []  184.47 186.57 0 top
NOREF#644  -  []  155.57 272.6 90 top
NOREF#645  -  []  411.52 146.33 90 top
NOREF#646  -  []  237.66 224.74 0 top
NOREF#647  -  []  310.73 247.93 0 top
NOREF#648  -  []  449.99 217.9 0 top
NOREF#649  -  []  410.84 180.15 90 top
NOREF#650  -  []  208.98 259.8 90 top
NOREF#651  -  []  250.73 205.55 0 top
NOREF#652  -  []  388.66 139.89 0 top
NOREF#653  -  []  339.46 288.86 90 top
NOREF#654  -  []  240.5 288.61 0 top
NOREF#655  -  []  256.77 225.04 90 top
NOREF#656  -  []  199.33 257.62 90 top
NOREF#657  -  []  272.55 241.37 0 top
NOREF#658  -  []  341.48 286.96 0 top
NOREF#659  -  []  483.17 130.26 90 top
NOREF#660  -  []  339.33 205.55 0 top
NOREF#661  -  []  375.73 194.78 90 top
NOREF#662  -  []  385.93 144.98 0 top
NOREF#663  -  []  404.15 241.11 0 top
NOREF#664  -  []  399.07 208.91 90 top
NOREF#665  -  []  262.36 223.82 90 top
NOREF#666  -  []  396.55 257.37 0 top
NOREF#667  -  []  122.15 195.15 0 top
NOREF#668  -  []  251.62 265.56 90 top
NOREF#669  -  []  297.71 216.09 0 top
NOREF#670  -  []  167.7 260.9 90 top
NOREF#671  -  []  93.02 247.21 90 top
NOREF#672  -  []  331.62 265.55 0 top
NOREF#673  -  []  119.7 238.84 0 top
NOREF#674  -  []  116.27 178.64 0 top
NOREF#675  -  []  184.47 258.7 90 top
NOREF#676  -  []  334.29 205.56 90 top
NOREF#677  -  []  399.99 164.91 90 top
NOREF#678  -  []  199.33 240.28 90 top
NOREF#679  -  []  192.47 177.76 90 top
NOREF#680  -  []  422.7 163.64 0 top
NOREF#681  -  []  223.56 245.29 90 top
NOREF#682  -  []  369.38 224.6 0 top
NOREF#683  -  []  194.09 173.86 90 top
NOREF#684  -  []  326.17 131.69 90 top
NOREF#685  -  []  184.47 159.65 0 top
NOREF#686  -  []  66.26 287.84 90 top
NOREF#687  -  []  167.7 149.48 90 top
NOREF#688  -  []  338.11 288.86 0 top
NOREF#689  -  []  237.57 269.63 90 top
NOREF#690  -  []  182.82 175.58 90 top
NOREF#691  -  []  238.45 197.01 0 top
NOREF#692  -  []  192.47 175.56 90 top
NOREF#693  -  []  378.33 209.11 0 top
NOREF#694  -  []  226.83 209.63 90 top
NOREF#695  -  []  328.96 164.74 0 top
NOREF#696  -  []  263.83 231.63 90 top
NOREF#697  -  []  327.57 204.65 90 top
NOREF#698  -  []  330.73 264.35 90 top
NOREF#699  -  []  325.92 131.64 0 top
NOREF#700  -  []  459.28 227 90 top
NOREF#701  -  []  167.7 204.09 90 top
NOREF#702  -  []  408.63 242.38 90 top
NOREF#703  -  []  230.43 248.88 90 top
NOREF#704  -  []  459.24 175.86 0 top
NOREF#705  -  []  182.57 240.28 90 top
NOREF#706  -  []  201.66 186.02 90 top
NOREF#707  -  []  485.36 289.48 90 top
NOREF#708  -  []  511.59 291.28 90 top
NOREF#709  -  []  330.74 164.74 0 top
NOREF#710  -  []  383.09 257.11 0 top
NOREF#711  -  []  419.47 273.37 90 top
NOREF#712  -  []  262.36 225.04 90 top
NOREF#713  -  []  343.31 164.74 0 top
NOREF#714  -  []  351.34 249.5 0 top
NOREF#715  -  []  313.56 144.34 90 top
NOREF#716  -  []  397.55 209.41 90 top
NOREF#717  -  []  175.8 228.97 90 top
NOREF#718  -  []  310.43 246.34 90 top
NOREF#719  -  []  250.73 205.56 90 top
NOREF#720  -  []  393.19 255.21 90 top
NOREF#721  -  []  399.67 139.89 0 top
NOREF#722  -  []  448.94 273.87 90 top
NOREF#723  -  []  168.13 132.17 90 top
NOREF#724  -  []  475.36 127 90 top
NOREF#725  -  []  201.49 173.11 0 top
NOREF#726  -  []  165.8 254 0 top
NOREF#727  -  []  473.79 196.21 0 top
NOREF#728  -  []  465.45 292.92 90 top
NOREF#729  -  []  343.31 224.72 0 top
NOREF#730  -  []  375.22 180.15 0 top
NOREF#731  -  []  201.49 165.4 90 top
NOREF#732  -  []  328.96 224.74 0 top
NOREF#733  -  []  374.34 210.38 90 top
NOREF#734  -  []  318.3 163.52 90 top
NOREF#735  -  []  230.43 247.61 0 top
NOREF#736  -  []  392.73 188.15 0 top
NOREF#737  -  []  96.33 238.84 0 top
NOREF#738  -  []  230.43 193.37 90 top
NOREF#739  -  []  397.8 146.43 90 top
NOREF#740  -  []  412.79 209.06 90 top
NOREF#741  -  []  411.26 179.7 90 top
NOREF#742  -  []  404.24 154.88 0 top
NOREF#743  -  []  372.72 161.49 0 top
NOREF#744  -  []  272.24 189.18 90 top
NOREF#745  -  []  377.32 171.39 0 top
NOREF#746  -  []  165.8 144.78 90 top
NOREF#747  -  []  471.21 219.38 90 top
NOREF#748  -  []  118.45 234.24 90 top
NOREF#749  -  []  383.83 194.68 90 top
NOREF#750  -  []  310.73 249.2 0 top
NOREF#751  -  []  209.23 218.65 90 top
NOREF#752  -  []  309.21 186.34 0 top
NOREF#753  -  []  313.98 131.09 90 top
NOREF#754  -  []  352.25 244.86 90 top
NOREF#755  -  []  252.51 204.35 90 top
NOREF#756  -  []  175.7 257.6 90 top
NOREF#757  -  []  310.83 224.63 0 top
NOREF#758  -  []  168.69 273.5 90 top
NOREF#759  -  []  127.59 211.59 90 top
NOREF#760  -  []  333.4 205.56 0 top
NOREF#761  -  []  167.7 190.12 90 top
NOREF#762  -  []  319.15 296.86 0 top
NOREF#763  -  []  473.79 234.49 90 top
NOREF#764  -  []  249.85 224.72 0 top
NOREF#765  -  []  343.63 223.82 90 top
NOREF#766  -  []  383.09 224.85 0 top
NOREF#767  -  []  463.61 179.15 0 top
NOREF#768  -  []  167.7 233.47 90 top
NOREF#769  -  []  275.28 290.13 90 top
NOREF#770  -  []  250.17 225.04 90 top
NOREF#771  -  []  367.13 287.22 0 top
NOREF#772  -  []  409.74 163.69 90 top
NOREF#773  -  []  285.71 280.1 0 top
NOREF#774  -  []  238.3 163.52 90 top
NOREF#775  -  []  177.33 160.4 90 top
NOREF#776  -  []  273.24 272.1 0 top
NOREF#777  -  []  210.86 228.47 90 top
NOREF#778  -  []  339.65 264.65 90 top
NOREF#779  -  []  230.43 188.88 0 top
NOREF#780  -  []  155.57 291.65 90 top
NOREF#781  -  []  351.04 241.69 0 top
NOREF#782  -  []  327.25 264.35 90 top
NOREF#783  -  []  399.8 207.46 90 top
NOREF#784  -  []  290.11 280.1 0 top
NOREF#785  -  []  339.33 205.56 0 top
NOREF#786  -  []  409.74 180.2 90 top
NOREF#787  -  []  166.06 203.01 90 top
NOREF#788  -  []  402.14 146.88 0 top
NOREF#789  -  []  118.7 222.88 0 top
NOREF#790  -  []  119.99 214.79 0 top
NOREF#791  -  []  168.69 290.01 90 top
NOREF#792  -  []  200.98 255.15 90 top
NOREF#793  -  []  371.48 249.11 0 top
NOREF#794  -  []  184.47 214 90 top
NOREF#795  -  []  215.96 237.06 0 top
NOREF#796  -  []  405.93 256.92 90 top
NOREF#797  -  []  406.44 154.88 0 top
NOREF#798  -  []  257.9 186.35 90 top
NOREF#799  -  []  412.36 209.61 90 top
NOREF#800  -  []  303.15 271.32 90 top
NOREF#801  -  []  11.6 261.68 90 top
NOREF#802  -  []  410.27 257.37 0 top
NOREF#803  -  []  201.49 173.11 90 top
NOREF#804  -  []  341.63 173.83 90 top
NOREF#805  -  []  352.24 249.18 90 top
NOREF#806  -  []  341.63 195.43 90 top
NOREF#807  -  []  167.7 138.47 90 top
NOREF#808  -  []  224.65 211.67 0 top
NOREF#809  -  []  413.96 182.44 90 top
NOREF#810  -  []  108.01 214.71 0 top
NOREF#811  -  []  312.21 131.64 0 top
NOREF#812  -  []  271.04 249.18 0 top
NOREF#813  -  []  373.32 164.66 90 top
NOREF#814  -  []  104.18 191.95 0 top
NOREF#815  -  []  272.55 183.91 0 top
NOREF#816  -  []  401.87 139.89 0 top
NOREF#817  -  []  326.43 288.41 90 top
NOREF#818  -  []  252.51 265.56 0 top
NOREF#819  -  []  271.04 189.82 0 top
NOREF#820  -  []  451.68 186.77 0 top
NOREF#821  -  []  199.59 243.9 90 top
NOREF#822  -  []  175.7 182.06 90 top
NOREF#823  -  []  461.96 217.98 0 top
NOREF#824  -  []  167.7 219.75 90 top
NOREF#825  -  []  473.7 219.66 90 top
NOREF#826  -  []  175.7 216.45 90 top
NOREF#827  -  []  401.52 210.88 90 top
NOREF#828  -  []  259.33 265.55 0 top
NOREF#829  -  []  167.7 174.46 90 top
NOREF#830  -  []  375.22 163.39 0 top
NOREF#831  -  []  343.63 165.04 90 top
NOREF#832  -  []  272.55 243.91 0 top
NOREF#833  -  []  408.63 274.64 90 top
NOREF#834  -  []  392.47 224.3 90 top
NOREF#835  -  []  298.13 274.06 90 top
NOREF#836  -  []  263.63 165.04 90 top
NOREF#837  -  []  256.77 163.82 90 top
NOREF#838  -  []  401.89 163.64 0 top
NOREF#839  -  []  419.9 154.88 0 top
NOREF#840  -  []  355.89 130.17 90 top
NOREF#841  -  []  182.57 199.39 0 top
NOREF#842  -  []  263.71 288.86 0 top
NOREF#843  -  []  351.34 243.91 0 top
NOREF#844  -  []  271.34 242.64 0 top
NOREF#845  -  []  518.38 292.92 90 top
NOREF#846  -  []  107.02 179.19 0 top
NOREF#847  -  []  271.34 243.91 0 top
NOREF#848  -  []  218.13 274.06 90 top
NOREF#849  -  []  225.83 264.31 0 top
NOREF#850  -  []  460.89 217.9 90 top
NOREF#851  -  []  111.54 287.84 90 top
NOREF#852  -  []  201.23 233.47 90 top
NOREF#853  -  []  272.24 184.86 90 top
NOREF#854  -  []  392.47 240.56 90 top
NOREF#855  -  []  272.25 244.86 90 top
NOREF#856  -  []  94.68 234.24 0 top
NOREF#857  -  []  478.57 257.36 90 top
NOREF#858  -  []  346.27 129.42 90 top
NOREF#859  -  []  528.1 273.87 90 top
NOREF#860  -  []  310.43 253.37 90 top
NOREF#861  -  []  184.47 192.32 90 top
NOREF#862  -  []  306.71 152.34 0 top
NOREF#863  -  []  246.23 233.13 0 top
NOREF#864  -  []  308.36 202.16 45 top
NOREF#865  -  []  382.47 133.16 90 top
NOREF#866  -  []  290.64 288.86 0 top
NOREF#867  -  []  511.59 257.36 90 top
NOREF#868  -  []  308.91 139.64 0 top
NOREF#869  -  []  472.86 210.36 90 top
NOREF#870  -  []  385.19 289.12 0 top
NOREF#871  -  []  182.57 226.57 0 top
NOREF#872  -  []  319.33 236.03 0 top
NOREF#873  -  []  230.43 253.37 90 top
NOREF#874  -  []  308.91 152.34 0 top
NOREF#875  -  []  276.4 147.38 0 top
NOREF#876  -  []  272.25 245.5 0 top
NOREF#877  -  []  337.9 246.99 0 top
NOREF#878  -  []  384.59 162.94 90 top
NOREF#879  -  []  373.68 232.6 0 top
NOREF#880  -  []  264.54 143.19 0 top
NOREF#881  -  []  382.82 180.15 0 top
NOREF#882  -  []  453.88 239.34 0 top
NOREF#883  -  []  309.21 246.34 0 top
NOREF#884  -  []  381.2 274.38 90 top
NOREF#885  -  []  310.73 186.66 0 top
NOREF#886  -  []  230.41 193.37 90 top
NOREF#887  -  []  405.42 131.94 90 top
NOREF#888  -  []  378.33 217.11 0 top
